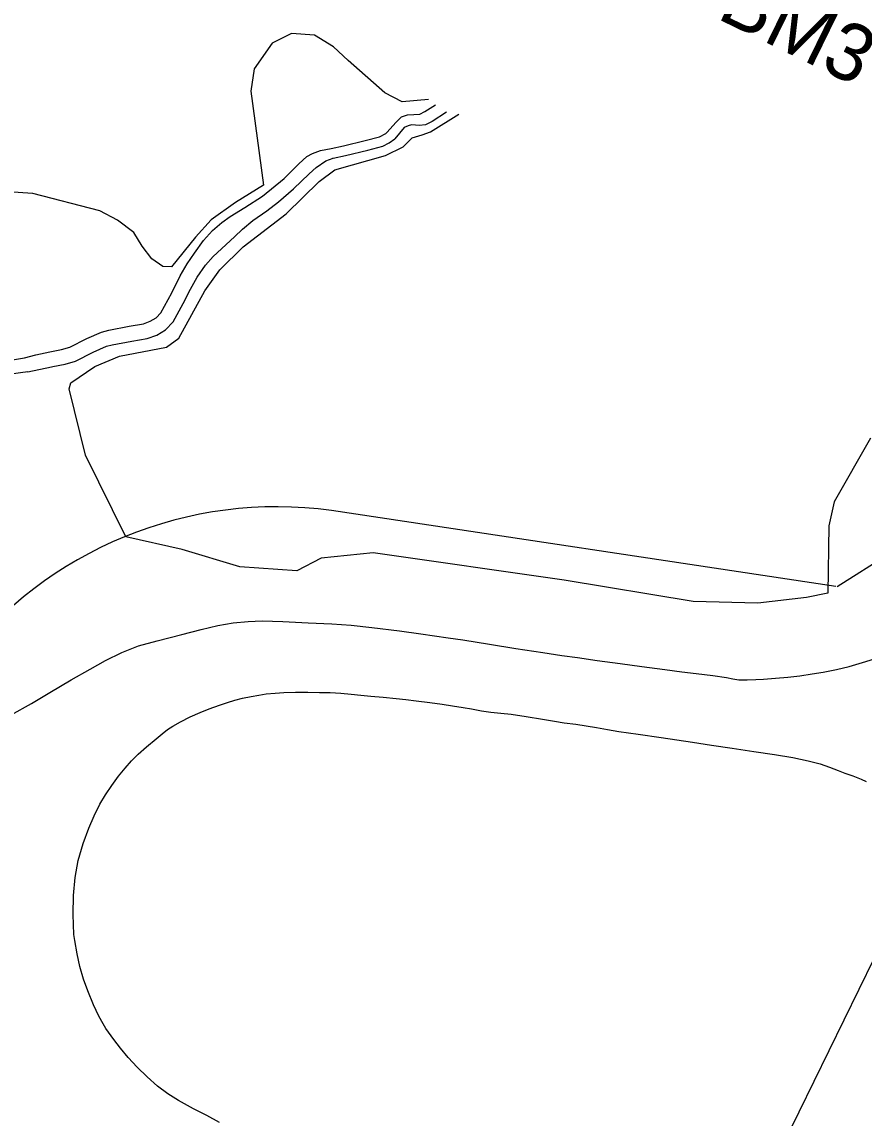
# Model space of a CAD drawing. Extents: x 1517485 to 1521905, y 636528 to 640355.
# Drawn here: x 1520112.8 to 1520407.4, y 638285.4 to 638668.8 of the extents above; entities that cross this region are included whole.
import ezdxf

# ---------------------------------------------------------------- set-up
doc = ezdxf.new("R2010")
doc.units = 0
for name, color, linetype in [('CTL Vertical Benchmark Text', 7, 'Continuous'), ('Exist Hydro Stream or Body of Water', 7, 'Continuous'), ('Exist Right of Way Line', 7, 'Continuous'), ('Exist Roads EOP', 7, 'Continuous'), ('Exist Vegetation Woods Line', 7, 'Continuous'), ('Scratch_Level_3', 7, 'Continuous')]:
    doc.layers.add(name, color=color, linetype=linetype)

msp = doc.modelspace()

# ---------------------------------------------------------------- linework, layer by layer
at = {"layer": 'Exist Hydro Stream or Body of Water'}
for p, q in [((1520241.27, 638626.48), (1520243.17, 638627.9)), ((1520209.63, 638619.11), (1520204.49, 638614.03)), ((1520213.21, 638615.69), (1520207.77, 638610.44)), ((1520182.66, 638598.65), (1520185.56, 638600.73)), ((1520187.07, 638593.58), (1520189.88, 638596.26)), ((1520114.82, 638546.45), (1520123.05, 638548.13))]:
    msp.add_line(p, q, dxfattribs=at)
for points in [[(1520240.5, 638630.21), (1520243.56, 638633.57), (1520245.58, 638635.6), (1520247.62, 638636.3), (1520249.91, 638636.4), (1520251.95, 638636.52), (1520253.69, 638637.41), (1520257.44, 638639.81)], [(1520261.32, 638637.2), (1520256.25, 638633.96), (1520253.98, 638632.84), (1520251.73, 638632.55), (1520250.43, 638632.74), (1520249.08, 638632.77), (1520247.84, 638632.45), (1520246.51, 638631.86), (1520243.17, 638627.9)], [(1520209.63, 638619.11), (1520212.47, 638621.74), (1520214.41, 638622.72), (1520217.26, 638623.77), (1520220.95, 638624.58), (1520225.25, 638625.4), (1520232.87, 638627.35), (1520237.84, 638628.62), (1520240.04, 638629.75), (1520240.5, 638630.21)], [(1520221.46, 638621.15), (1520221.65, 638621.19), (1520226, 638622.02), (1520233.73, 638623.99), (1520239.07, 638625.36), (1520241.27, 638626.48)], [(1520213.21, 638615.69), (1520215.74, 638617.86), (1520219.06, 638620.17), (1520221.65, 638621.19)], [(1520185.56, 638600.73), (1520190.73, 638603.86), (1520196.93, 638607.86), (1520204.49, 638614.03)], [(1520189.88, 638596.26), (1520193.56, 638599.39), (1520198.49, 638602.71), (1520202.53, 638605.89), (1520207.77, 638610.44)], [(1520113.66, 638551.31), (1520117.59, 638552.39), (1520122.51, 638553.4), (1520126.64, 638554.23), (1520129.55, 638555.1), (1520135.45, 638558.03), (1520140.62, 638560.33), (1520143.19, 638561.02), (1520150.31, 638562.36), (1520155.26, 638563.21), (1520157.68, 638564.09), (1520159.71, 638565.25), (1520161.33, 638567.03), (1520165.16, 638574.08), (1520168.17, 638580.03), (1520170.58, 638584.22), (1520173.1, 638587.94), (1520176.33, 638592.36), (1520179.44, 638595.89), (1520182.66, 638598.65)], [(1520171.13, 638574.22), (1520174.1, 638579.55), (1520177.03, 638583.7), (1520179.65, 638586.71), (1520187.07, 638593.58)], [(1520123.05, 638548.13), (1520123.55, 638548.24), (1520127.92, 638549.11), (1520131.5, 638550.18), (1520137.69, 638553.26), (1520142.38, 638555.35), (1520144.35, 638555.88), (1520151.25, 638557.17), (1520156.62, 638558.1), (1520159.9, 638559.29), (1520163.04, 638561.09), (1520165.66, 638563.95), (1520169.82, 638571.64), (1520171.13, 638574.22)], [(1520096.22, 638546.71), (1520101.74, 638548.73), (1520107.41, 638550.25), (1520113.66, 638551.31)], [(1520114.82, 638546.45), (1520108.84, 638545.59), (1520104.45, 638544.21), (1520098.32, 638541.51)]]:
    msp.add_lwpolyline(points, dxfattribs=at)
at = {"layer": 'Exist Right of Way Line'}
for p, q in [((1520397.94, 638471.31), (1520456.28, 638508.46)), ((1520397.53, 638471.37), (1520221.07, 638497.91))]:
    msp.add_line(p, q, dxfattribs=at)
msp.add_arc((1520201.87, 638359.23), 140, 82.1191, 142.5845, dxfattribs=at)
at = {"layer": 'Exist Roads EOP'}
for points in [[(1520109, 638426.45), (1520116.08, 638430.38), (1520122.57, 638434.21), (1520129.96, 638438.67), (1520136.61, 638442.47), (1520141.97, 638445.43), (1520147.76, 638448.31), (1520153.56, 638450.53), (1520160.09, 638452.32), (1520168.68, 638454.59), (1520175.48, 638456.27), (1520181.27, 638457.7), (1520186.62, 638458.67), (1520191.92, 638459.15), (1520196.82, 638459.31), (1520204, 638459.1), (1520212.93, 638458.67), (1520221.16, 638458.27), (1520227.91, 638457.82), (1520235.16, 638456.98), (1520244.86, 638455.79), (1520252.34, 638454.75), (1520261.85, 638453.42), (1520267.03, 638452.64), (1520276.34, 638451.22), (1520285.57, 638449.71), (1520295.02, 638448.2), (1520301.59, 638447.22), (1520307.15, 638446.46), (1520314.03, 638445.49), (1520322.1, 638444.37), (1520329.66, 638443.32), (1520337.66, 638442.27), (1520343.57, 638441.5), (1520348.59, 638440.86), (1520354.52, 638440.19), (1520359.23, 638439.5), (1520361.46, 638439.03), (1520363.58, 638438.75), (1520366.51, 638438.64), (1520369.49, 638438.79), (1520372.16, 638438.92), (1520376.44, 638439.25), (1520380.71, 638439.67), (1520384.92, 638440.15), (1520389.26, 638440.78), (1520393.01, 638441.43), (1520397.77, 638442.36), (1520402.19, 638443.41), (1520406.83, 638444.75), (1520411.02, 638446.04)], [(1520181.82, 638283.9), (1520177.4, 638286.31), (1520172.75, 638288.65), (1520167.52, 638291.53), (1520163.86, 638293.86), (1520160.23, 638296.62), (1520156.54, 638299.84), (1520153.02, 638303.27), (1520149.95, 638306.59), (1520147.21, 638309.85), (1520144.92, 638312.94), (1520142.17, 638316.76), (1520141.16, 638318.33), (1520139.62, 638321.11), (1520137.78, 638325.06), (1520135.76, 638329.9), (1520134.31, 638333.97), (1520133.03, 638338.46), (1520132.11, 638342.87), (1520131.24, 638347.54), (1520130.91, 638349.64), (1520130.74, 638356.58), (1520130.84, 638363.26), (1520131.33, 638369.51), (1520132.48, 638375.51), (1520134.22, 638381.48), (1520136.16, 638386.84), (1520138.02, 638391.15), (1520140.06, 638395.18), (1520141.95, 638398.45), (1520144.2, 638401.73), (1520146.6, 638404.97), (1520148.85, 638407.77), (1520151.11, 638410.31), (1520153.45, 638412.68), (1520156.39, 638415.3), (1520159.69, 638418.09), (1520161.77, 638419.8), (1520163.7, 638421.27), (1520165.51, 638422.47), (1520168.24, 638424.01), (1520171.64, 638425.72), (1520175.07, 638427.25), (1520178.29, 638428.59), (1520181.85, 638429.86), (1520184.71, 638430.78), (1520187.25, 638431.59), (1520189.93, 638432.29), (1520193.01, 638432.92), (1520195.65, 638433.39), (1520198.18, 638433.79), (1520201.3, 638434.09), (1520204.41, 638434.28), (1520208.47, 638434.35), (1520212.73, 638434.37), (1520216.84, 638434.29), (1520220.56, 638434.23), (1520224.27, 638434.05), (1520227.92, 638433.71), (1520231.37, 638433.35), (1520234.87, 638433), (1520239.18, 638432.62), (1520243.71, 638432.13), (1520247.05, 638431.81), (1520250.65, 638431.37), (1520255.47, 638430.73), (1520259.79, 638430.14), (1520263.34, 638429.65), (1520267.14, 638428.99), (1520269.99, 638428.52), (1520273.5, 638427.91), (1520276.79, 638427.42), (1520280.29, 638427.04), (1520283.94, 638426.65), (1520289.18, 638425.91), (1520294.83, 638424.97), (1520299.02, 638424.19), (1520302.51, 638423.71), (1520306.5, 638423.16), (1520313.77, 638422.04), (1520317.65, 638421.38), (1520321.55, 638420.65), (1520328.32, 638419.65), (1520336.34, 638418.51), (1520341.92, 638417.7), (1520347.36, 638416.86), (1520353.95, 638415.86), (1520361.23, 638414.8), (1520368.78, 638413.67), (1520375.98, 638412.64), (1520382.44, 638411.56), (1520387.76, 638410.42), (1520392.01, 638409.31), (1520395.27, 638408.21), (1520398.35, 638407), (1520400.64, 638406.11), (1520403.48, 638405.07), (1520406.33, 638403.95), (1520408.16, 638403.18)]]:
    msp.add_lwpolyline(points, dxfattribs=at)
at = {"layer": 'Exist Vegetation Woods Line'}
for points in [[(1520255, 638641.69), (1520245.79, 638640.8), (1520239.74, 638643.95), (1520226.87, 638655.27), (1520221.78, 638660.04), (1520215.12, 638664.2), (1520207.09, 638664.76), (1520200.36, 638661.36), (1520193.95, 638652.36), (1520192.89, 638644.59), (1520197.29, 638611.68), (1520187.49, 638605.58), (1520179.01, 638599.59), (1520173.52, 638593.53), (1520165.09, 638583.16), (1520162.1, 638583.26), (1520158.17, 638585.96), (1520154.77, 638590.37), (1520151.86, 638595.18), (1520146.19, 638599.5), (1520139.96, 638602.74), (1520116.63, 638608.74), (1520097.42, 638610.12)], [(1520222.19, 638617.05), (1520239.91, 638622.03), (1520246.13, 638625.11), (1520249.26, 638628.22), (1520252.75, 638629.27), (1520255.7, 638630.36), (1520265.66, 638636.53)], [(1520409.58, 638523.26), (1520396.91, 638500.93), (1520395.02, 638492.54), (1520394.75, 638469.05), (1520387.28, 638467.54), (1520370.21, 638465.51), (1520347.54, 638466.11), (1520302.4, 638473.51), (1520235.63, 638483.09), (1520217.39, 638481.22), (1520208.89, 638476.82), (1520189.01, 638478.22), (1520168.77, 638484.27), (1520149.11, 638488.76), (1520134.96, 638517.22), (1520129.33, 638540.51), (1520129.91, 638542.59), (1520138.3, 638548.24), (1520146.92, 638551.95), (1520163.38, 638555.08), (1520167.61, 638558.14), (1520176.79, 638574.73), (1520181.96, 638582.07), (1520190.1, 638590.11), (1520205.24, 638601.64), (1520216.71, 638612.95), (1520222.19, 638617.05)]]:
    msp.add_lwpolyline(points, dxfattribs=at)
at = {"layer": 'Scratch_Level_3'}
msp.add_line((1520770.84, 639077.45), (1520017.02, 637536.16), dxfattribs=at)

# ---------------------------------------------------------------- texts
at = {"layer": 'CTL Vertical Benchmark Text'}
msp.add_text('BM3', height=20, rotation=333.9377, dxfattribs=at).set_placement((1520355.36, 638670.25))

doc.saveas('drawing.dxf')
